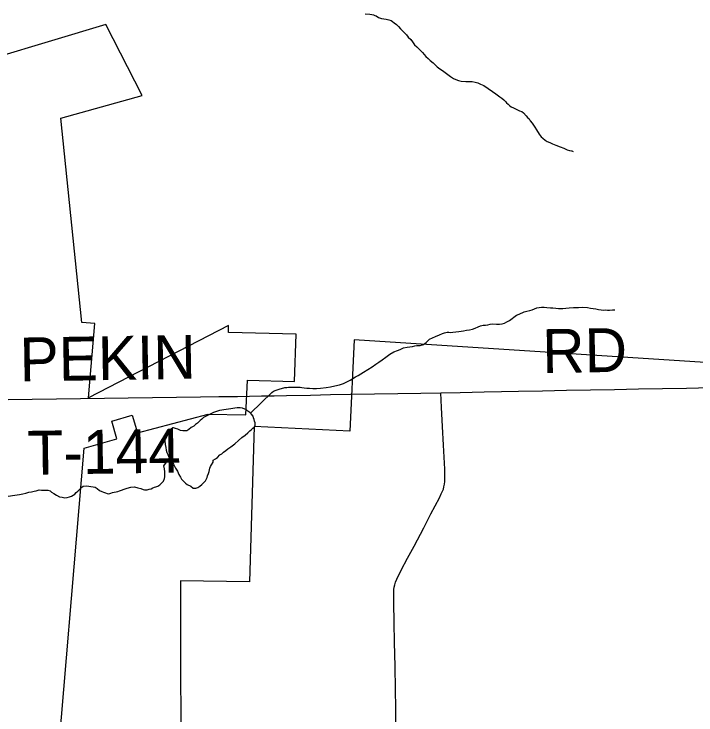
# Model space of a CAD drawing. Extents: x -11.4 to 84.1, y 11.1 to 59.
# Drawn here: x 28.501 to 29.384, y 44.72 to 45.628 of the extents above; entities that cross this region are included whole.
import ezdxf

# ---------------------------------------------------------------- set-up
doc = ezdxf.new("R2010")
doc.units = 0
for name, color, linetype in [('GM_X_Corporation', 7, 'Continuous'), ('GM_X_Minor_Lake', 7, 'Continuous'), ('GM_X_Minor_River', 7, 'Continuous'), ('GM_X_Township_Road', 7, 'Continuous'), ('GM_X_Township_Road_Text', 7, 'Continuous')]:
    doc.layers.add(name, color=color, linetype=linetype)

msp = doc.modelspace()

# ---------------------------------------------------------------- linework, layer by layer
at = {"layer": 'GM_X_Corporation'}
for points in [[(28.55271, 44.60006), (28.59239, 45.06585), (28.63464, 45.07807), (28.62801, 45.101), (28.65438, 45.10864), (28.66101, 45.08571), (28.75283, 45.10986), (28.80139, 45.10889), (28.80354, 45.15401), (28.8643, 45.15209), (28.86641, 45.21341), (28.77895, 45.21585), (28.77894, 45.22475), (28.59796, 45.13112), (28.60615, 45.22724), (28.58905, 45.22843), (28.56197, 45.493), (28.66736, 45.52251), (28.62013, 45.61429), (28.40468, 45.54971)], [(29.41732, 44.66567), (29.44937, 45.17354), (28.94184, 45.20598), (28.93626, 45.08806), (28.81223, 45.094), (28.80607, 44.89278), (28.7167, 44.89422), (28.71711, 44.59705)]]:
    msp.add_lwpolyline(points, dxfattribs=at)
at = {"layer": 'GM_X_Minor_Lake'}
for points in [[(28.69757, 45.08446), (28.69688, 45.07989), (28.69658, 45.07532), (28.69704, 45.07077), (28.69786, 45.06659), (28.6983, 45.06318), (28.69911, 45.06015), (28.7003, 45.05751), (28.70187, 45.05411), (28.70499, 45.0496), (28.70772, 45.04508), (28.71046, 45.04018), (28.71281, 45.03604), (28.71478, 45.03189), (28.71673, 45.0285), (28.7183, 45.02586), (28.71985, 45.02399), (28.72332, 45.02062), (28.72564, 45.01876), (28.73022, 45.01693), (28.73331, 45.01432), (28.73673, 45.014), (28.73937, 45.01518), (28.742, 45.01675), (28.74463, 45.01869), (28.74649, 45.021), (28.7491, 45.02371), (28.75058, 45.02601), (28.75131, 45.02793), (28.75203, 45.03022), (28.75312, 45.03328), (28.75384, 45.03557), (28.75456, 45.03787), (28.7549, 45.04016), (28.75563, 45.04207), (28.75711, 45.04437), (28.75895, 45.04783), (28.75929, 45.05049), (28.7623, 45.05206), (28.76493, 45.05401), (28.76791, 45.0571), (28.77017, 45.05866), (28.77241, 45.0606), (28.77541, 45.06293), (28.77804, 45.06487), (28.78217, 45.0676), (28.78704, 45.07148), (28.79191, 45.07575), (28.7964, 45.07962), (28.80053, 45.08273), (28.80389, 45.08583), (28.80651, 45.08816), (28.80876, 45.09009), (28.81063, 45.09202), (28.81288, 45.09358), (28.8136, 45.09588), (28.81356, 45.09854), (28.81276, 45.10081), (28.81234, 45.10308), (28.81154, 45.10535), (28.81113, 45.10724), (28.80842, 45.11024), (28.80649, 45.11211), (28.80418, 45.11397), (28.80226, 45.11546), (28.80034, 45.11657), (28.79728, 45.11766), (28.79424, 45.11799), (28.79234, 45.11796), (28.79044, 45.11793), (28.7874, 45.11788), (28.78475, 45.11746), (28.7821, 45.11703), (28.77907, 45.1166), (28.77604, 45.11617), (28.773, 45.11574), (28.77035, 45.11532), (28.76733, 45.11451), (28.76355, 45.11331), (28.75977, 45.1121), (28.74847, 45.10659), (28.74659, 45.10542), (28.74435, 45.10348), (28.74248, 45.10155), (28.74061, 45.1), (28.73873, 45.09845), (28.73648, 45.09651), (28.73424, 45.09457), (28.73085, 45.09261), (28.72747, 45.09028), (28.72523, 45.08834), (28.72333, 45.08831), (28.71991, 45.08825), (28.71686, 45.08896), (28.71342, 45.09043), (28.71036, 45.09152), (28.70769, 45.09224), (28.70717, 45.0923)], [(28.70717, 45.0923), (28.69757, 45.08446)]]:
    msp.add_lwpolyline(points, dxfattribs=at)
at = {"layer": 'GM_X_Minor_River'}
for points in [[(28.95584, 45.6283), (28.96193, 45.62764), (28.96459, 45.6273), (28.9665, 45.62695), (28.96841, 45.62622), (28.97032, 45.62549), (28.97339, 45.62364), (28.97722, 45.62218), (28.98293, 45.62114), (28.98674, 45.62044), (28.98941, 45.61972), (28.99133, 45.61824), (28.99365, 45.61637), (28.99633, 45.61451), (28.99904, 45.6119), (29.00175, 45.6089), (29.00445, 45.60628), (29.00677, 45.60366), (29.00947, 45.60104), (29.0118, 45.59804), (29.01489, 45.59505), (29.01722, 45.59204), (29.01994, 45.58828), (29.02265, 45.58567), (29.02496, 45.58342), (29.02728, 45.58118), (29.02999, 45.57818), (29.03231, 45.57556), (29.03463, 45.57293), (29.03734, 45.57032), (29.04004, 45.5677), (29.04389, 45.56472), (29.04659, 45.5621), (29.04929, 45.55949), (29.05237, 45.55688), (29.05583, 45.55465), (29.05929, 45.55243), (29.06313, 45.54983), (29.06659, 45.54722), (29.07043, 45.54462), (29.0735, 45.54315), (29.07655, 45.54206), (29.08037, 45.54099), (29.08607, 45.5407), (29.09025, 45.54077), (29.09443, 45.54046), (29.09824, 45.53976), (29.10167, 45.53905), (29.10512, 45.53721), (29.10933, 45.53538), (29.12085, 45.52758), (29.12508, 45.52461), (29.13008, 45.52089), (29.13277, 45.51903), (29.13547, 45.51679), (29.1374, 45.51492), (29.13895, 45.51305), (29.14088, 45.51118), (29.1428, 45.50969), (29.14511, 45.50783), (29.14779, 45.50673), (29.15047, 45.50525), (29.15315, 45.50377), (29.15583, 45.50268), (29.15889, 45.50159), (29.16081, 45.5001), (29.16429, 45.49635), (29.16623, 45.4941), (29.16816, 45.49224), (29.16973, 45.4896), (29.17205, 45.48659), (29.174, 45.48397), (29.17556, 45.48133)], [(29.17556, 45.48133), (29.17752, 45.47794), (29.18103, 45.47229), (29.18375, 45.46892), (29.18606, 45.46705), (29.18875, 45.46481), (29.19144, 45.46296), (29.19488, 45.46149), (29.19833, 45.46003), (29.20292, 45.4582), (29.20827, 45.45601), (29.21324, 45.45419), (29.21745, 45.45236), (29.2205, 45.45127), (29.22317, 45.45093), (29.22355, 45.45094), (29.22431, 45.45057), (29.22508, 45.4502)], [(28.80728, 45.11134), (28.83492, 45.13806), (28.83718, 45.13962), (28.84058, 45.14081), (28.84472, 45.1424), (28.85191, 45.14442), (28.85457, 45.14446), (28.85684, 45.14488), (28.86063, 45.14494), (28.86405, 45.145), (28.86709, 45.14505), (28.86937, 45.14471), (28.87165, 45.14474), (28.87394, 45.1444), (28.87698, 45.14407), (28.8804, 45.14375), (28.88383, 45.14342), (28.88801, 45.14311), (28.89295, 45.14319), (28.89826, 45.14366), (28.90546, 45.14454), (28.91115, 45.14539), (28.91682, 45.14663), (28.9225, 45.14786), (28.92778, 45.14985), (28.93231, 45.15182), (28.93645, 45.1538), (28.93983, 45.15613), (28.94359, 45.15848), (28.94698, 45.16005), (28.95036, 45.16201), (28.95375, 45.16435), (28.96502, 45.17138), (28.96953, 45.17449), (28.97366, 45.17722), (28.97779, 45.18033), (28.98266, 45.18384), (28.98792, 45.18772), (28.99319, 45.19047), (28.99771, 45.19245), (29.00111, 45.19365), (29.00564, 45.19562), (29.01017, 45.19684), (29.01358, 45.19727), (29.017, 45.19771), (29.02002, 45.19852), (29.02267, 45.19894), (29.02533, 45.19899), (29.02723, 45.19902), (29.03139, 45.20023), (29.03477, 45.20256), (29.03925, 45.20682), (29.04679, 45.21037), (29.05207, 45.21274), (29.05622, 45.21432), (29.05848, 45.21512), (29.06037, 45.21553), (29.06227, 45.21595), (29.06417, 45.21598), (29.06645, 45.21563), (29.06948, 45.21606), (29.07327, 45.21651), (29.07706, 45.21695), (29.08313, 45.21781), (29.08729, 45.21864), (29.09108, 45.21908), (29.09486, 45.2199), (29.09826, 45.22148), (29.10203, 45.22306), (29.10543, 45.22426), (29.10883, 45.22508), (29.11187, 45.22513), (29.11452, 45.22555), (29.11754, 45.22636), (29.12096, 45.2268), (29.1259, 45.2265), (29.1297, 45.22656), (29.13311, 45.227), (29.13613, 45.22781), (29.13915, 45.22938), (29.14291, 45.23134), (29.15191, 45.23795), (29.15531, 45.23953), (29.15719, 45.24032), (29.15983, 45.24151), (29.16172, 45.2423), (29.16512, 45.24311), (29.1689, 45.24432), (29.1723, 45.24513), (29.17532, 45.24632), (29.17834, 45.24752), (29.18137, 45.24794), (29.1844, 45.24838), (29.18782, 45.24843), (29.19125, 45.24811), (29.19581, 45.2478)], [(29.19581, 45.2478), (29.19885, 45.24747), (29.20265, 45.24715), (29.20608, 45.24683), (29.20912, 45.24688), (29.21178, 45.24654), (29.21557, 45.24699), (29.22012, 45.24744), (29.22581, 45.24792), (29.23189, 45.24802), (29.23758, 45.24849), (29.24366, 45.24783), (29.24747, 45.24713), (29.2509, 45.24681), (29.25433, 45.2461), (29.25776, 45.2454), (29.26156, 45.24508), (29.2646, 45.24475), (29.26764, 45.2448), (29.26955, 45.24445), (29.27221, 45.24449), (29.276, 45.24494), (29.27865, 45.24498), (29.27903, 45.24499)], [(28.49381, 45.00392), (28.50253, 45.0052), (28.50859, 45.00606), (28.51275, 45.00689), (28.51654, 45.00772), (28.52069, 45.00892), (28.52411, 45.00936), (28.52751, 45.01018), (28.53016, 45.0106), (28.53394, 45.01181), (28.53698, 45.01147), (28.53964, 45.01152), (28.54268, 45.01157), (28.54496, 45.0116), (28.54801, 45.01089), (28.54994, 45.00902), (28.55301, 45.00717), (28.55647, 45.00495), (28.56029, 45.00311), (28.56372, 45.00241), (28.56715, 45.0017), (28.57018, 45.00213), (28.57321, 45.00294), (28.57586, 45.00375), (28.57811, 45.00492), (28.57999, 45.00648), (28.58186, 45.00841), (28.5841, 45.01035), (28.58672, 45.01305), (28.58896, 45.01537), (28.59083, 45.01654), (28.59462, 45.01698), (28.59843, 45.01667), (28.60643, 45.01528), (28.60911, 45.0138), (28.61219, 45.01119), (28.61488, 45.00971), (28.61717, 45.00899), (28.61985, 45.00789), (28.62214, 45.00717), (28.62404, 45.00682), (28.62669, 45.00763), (28.62895, 45.00842), (28.63122, 45.00884), (28.6335, 45.00926), (28.63577, 45.00968), (28.63804, 45.01047), (28.64067, 45.01166), (28.64407, 45.01285), (28.64785, 45.01406), (28.65239, 45.01527), (28.65732, 45.01573), (28.66151, 45.01466), (28.66571, 45.01359), (28.66839, 45.01249), (28.67029, 45.01214), (28.67372, 45.01182), (28.67636, 45.01263), (28.679, 45.01343), (28.68126, 45.01461), (28.68315, 45.0154), (28.68504, 45.01581), (28.68769, 45.01661), (28.69031, 45.01856), (28.69331, 45.02127), (28.69479, 45.0232), (28.69626, 45.02664), (28.6966, 45.02893), (28.69654, 45.03235), (28.69649, 45.03539), (28.69604, 45.03919), (28.69522, 45.04298), (28.70262, 45.05303)]]:
    msp.add_lwpolyline(points, dxfattribs=at)
at = {"layer": 'GM_X_Township_Road'}
for points in [[(28.49401, 45.12885), (28.52508, 45.12928), (28.55615, 45.12972), (28.58722, 45.13015), (28.61829, 45.13058), (28.64935, 45.13102), (28.68042, 45.13144), (28.71149, 45.13188), (28.74256, 45.13231), (28.76666, 45.13264), (28.79075, 45.13298), (28.82181, 45.13355), (28.83804, 45.13385), (28.85426, 45.13415), (28.88533, 45.13474), (28.91117, 45.13522), (28.93701, 45.13571), (28.96807, 45.13622), (28.99814, 45.13671), (29.0282, 45.13721), (29.05393, 45.13763), (29.07907, 45.13816), (29.11014, 45.13881), (29.13223, 45.13928), (29.15433, 45.13974), (29.1854, 45.14032), (29.21646, 45.1409), (29.24752, 45.14148), (29.27858, 45.14206), (29.30965, 45.14264), (29.34071, 45.14323), (29.37177, 45.1438), (29.40283, 45.14439)], [(28.99569, 44.70523), (28.99549, 44.72938), (28.99531, 44.75353), (28.99464, 44.78388), (28.99396, 44.81423), (28.99344, 44.84002), (28.99292, 44.8658), (28.99282, 44.87358), (28.99292, 44.87916), (28.99321, 44.88288), (28.99365, 44.88601), (28.99426, 44.88914), (28.99521, 44.8923), (28.99684, 44.89621), (29.00266, 44.90809), (29.0109, 44.92361), (29.01915, 44.93914), (29.03182, 44.96269), (29.041, 44.98092), (29.052, 45.00171), (29.05444, 45.00662), (29.05603, 45.01024), (29.05713, 45.01293), (29.05797, 45.01604), (29.05856, 45.01949), (29.05889, 45.02277), (29.05915, 45.02672), (29.05895, 45.03859), (29.05738, 45.06962), (29.05615, 45.094), (29.05491, 45.11838), (29.05393, 45.13763)]]:
    msp.add_lwpolyline(points, dxfattribs=at)

# ---------------------------------------------------------------- texts
at = {"layer": 'GM_X_Township_Road_Text'}
for s, rotation, p in [('RD', 0.98724, (29.18566, 45.16303)), ('PEKIN', 0.93574, (28.50901, 45.15219)), ('T-144', 0.84314, (28.51915, 45.03145))]:
    msp.add_text(s, height=0.056818, rotation=rotation, dxfattribs=at).set_placement(p)

doc.saveas('drawing.dxf')
